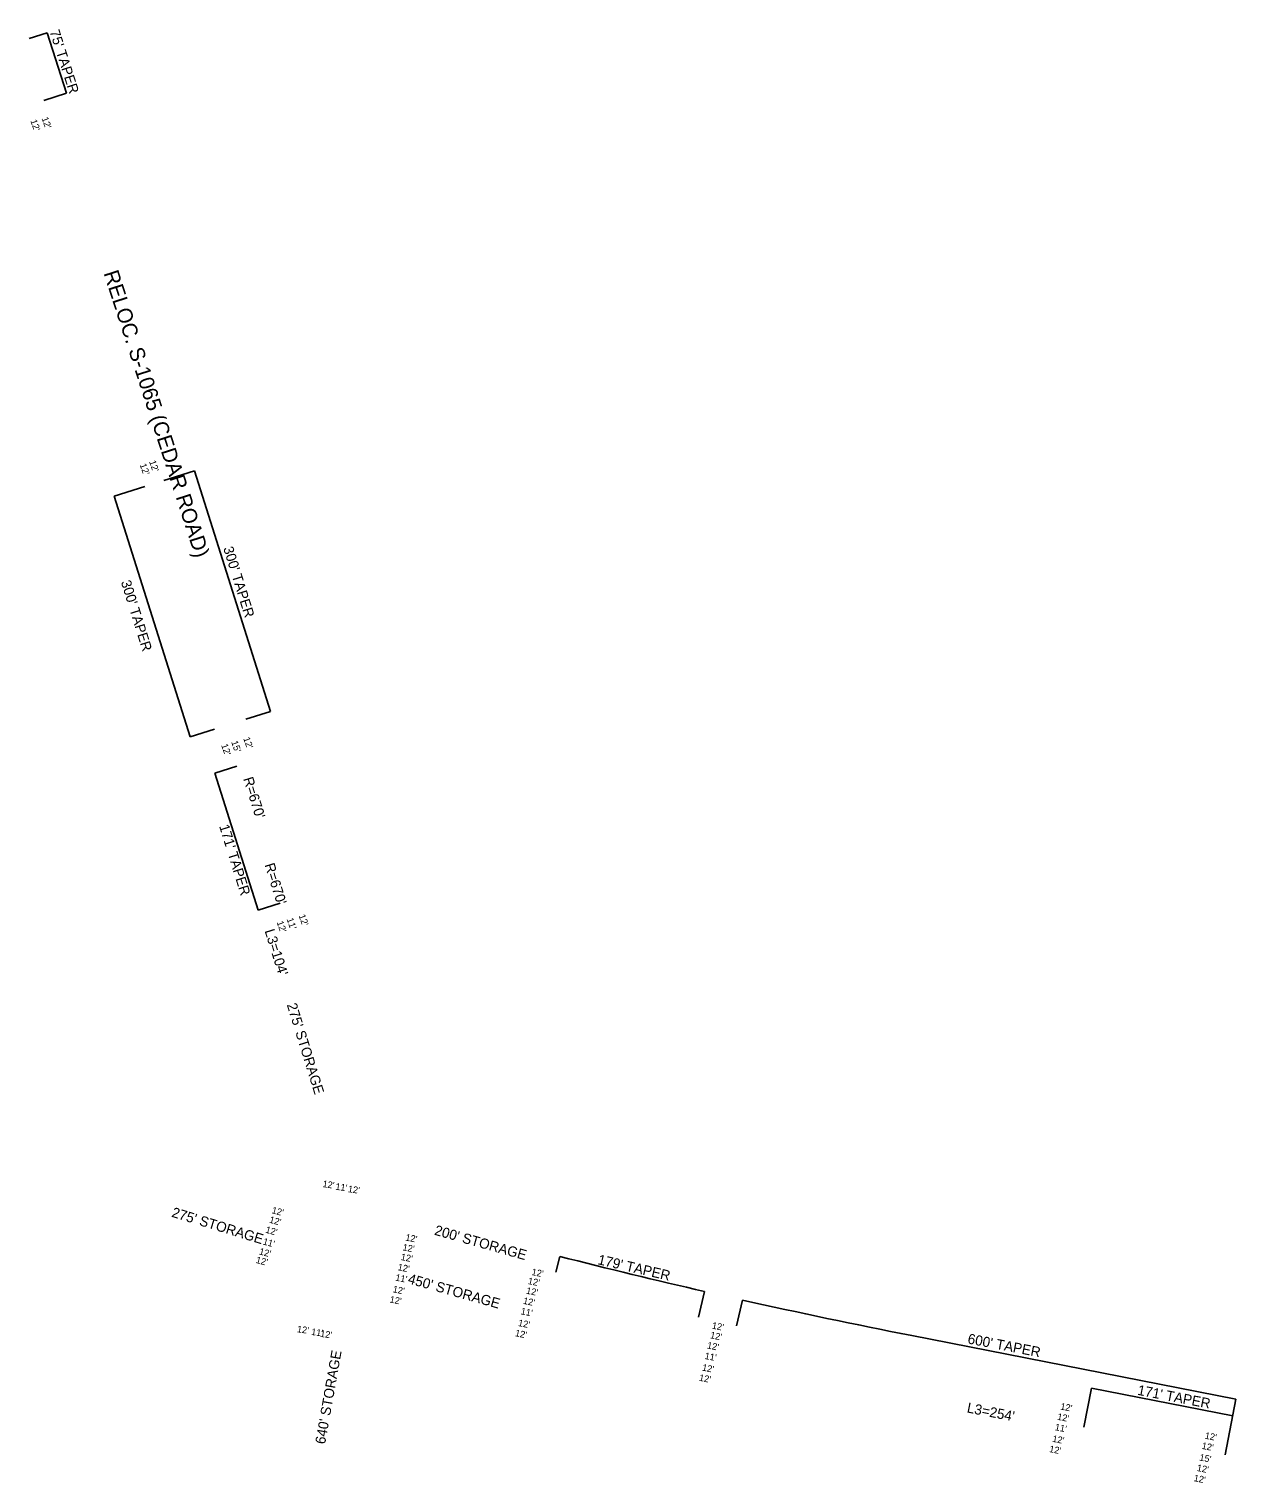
# Model space of a CAD drawing. Extents: x 1938363 to 1944069, y 778949 to 784066.
# Drawn here: x 1942634 to 1944069, y 779873 to 781602 of the extents above; entities that cross this region are included whole.
import ezdxf

# ---------------------------------------------------------------- set-up
doc = ezdxf.new("R2010")
doc.units = 0
doc.layers.add('RD_PD_Final_TX', color=7, linetype='Continuous')
doc.layers.add('RD_TX_RoadID', color=7, linetype='Continuous')

msp = doc.modelspace()

# ---------------------------------------------------------------- linework, layer by layer
at = {"layer": 'RD_PD_Final_TX'}
for p, q in [((1942633.6, 781590.7), (1942655.3, 781597.5)), ((1942655.3, 781597.5), (1942678, 781525.7)), ((1942651.3, 781517.2), (1942678, 781525.7)), ((1942830.3, 781076.7), (1942794, 781065.3)), ((1942830.3, 781076.7), (1942920.7, 780790.5)), ((1942771.2, 781058), (1942734.9, 781046.6)), ((1942734.9, 781046.6), (1942825.3, 780760.4)), ((1942920.7, 780790.5), (1942891.6, 780781.3)), ((1942854.4, 780769.6), (1942825.3, 780760.4)), ((1942880.9, 780725.5), (1942854.7, 780717.2)), ((1942854.7, 780717.2), (1942906.2, 780554.2)), ((1942932.4, 780562.4), (1942906.2, 780554.2)), ((1943260.2, 780123.5), (1943265, 780142.4)), ((1943430.2, 780070), (1943437.3, 780100.7)), ((1943475.4, 780059.7), (1943482.3, 780090.5)), ((1943683.7, 780048.2), (1944069.4, 779972.5)), ((1943888.6, 779939.2), (1943897.7, 779985.8)), ((1943897.7, 779985.8), (1944065.5, 779952.9)), ((1944056.4, 779906.3), (1944069.4, 779972.5))]:
    msp.add_line(p, q, dxfattribs=at)
for start, end in [(255.74647, 257.04964), (257.38869, 258.90156)]:
    msp.add_arc((1945184.2, 787697.4), 7795, start, end, dxfattribs=at)

# ---------------------------------------------------------------- texts
for s, height, rotation, p in [("75' TAPER", 12, 287.712, (1942657.9, 781599.2)), ("12'", 8, 289.542, (1942635, 781493.1)), ("12'", 8, 289.542, (1942648.4, 781496)), ("12'", 8, 289.542, (1942776.3, 781087.7)), ("12'", 8, 289.542, (1942765.1, 781083.9)), ("300' TAPER", 12, 287.3319, (1942864.5, 780984.7)), ("300' TAPER", 12, 287.3319, (1942742.7, 780944.6)), ("12'", 8, 289.542, (1942888.3, 780758.5)), ("12'", 8, 289.542, (1942862, 780750.5)), ("15'", 8, 289.542, (1942874, 780754.2)), ("R=670'", 12, 287.3319, (1942888.3, 780710.5)), ("171' TAPER", 12, 287.3319, (1942859.6, 780654.2)), ("R=670'", 12, 287.3319, (1942913.7, 780608.1)), ("12'", 8, 289.542, (1942928, 780539.8)), ("11'", 8, 289.542, (1942939.9, 780543.5)), ("12'", 8, 289.542, (1942954.2, 780547.7)), ("L3=104'", 12, 287.3319, (1942913.7, 780529.6)), ("275' STORAGE", 12, 287.2227, (1942940.1, 780441.7)), ("12'", 8, 351.606, (1942982.4, 780224.9)), ("11'", 8, 351.606, (1942997.7, 780221.8)), ("12'", 8, 351.606, (1943012.6, 780218.9)), ("275' STORAGE", 12, 343.0326, (1942802.4, 780189.7)), ("12'", 8, 345.0511, (1942918.8, 780182.6)), ("12'", 8, 345.0511, (1942921.7, 780193.9)), ("12'", 8, 345.0511, (1942914.3, 780170.7)), ("200' STORAGE", 12, 344.3329, (1943115, 780168.3)), ("11'", 8, 345.0511, (1942911.2, 780156.7)), ("12'", 8, 348.9016, (1943077.5, 780149.7)), ("12'", 8, 348.9016, (1943080.8, 780161.4)), ("12'", 8, 345.0511, (1942902.8, 780134.8)), ("12'", 8, 345.0511, (1942906.7, 780144.9)), ("12'", 8, 348.9016, (1943075.4, 780138.2)), ("179' TAPER", 12, 346.9376, (1943309.4, 780133.2)), ("11'", 8, 348.9016, (1943068.9, 780113.7)), ("12'", 8, 348.9016, (1943071.7, 780126.1)), ("450' STORAGE", 12, 344.3329, (1943083.4, 780110.6)), ("12'", 8, 348.9016, (1943231, 780120.3)), ("12'", 8, 348.9016, (1943065.8, 780099.8)), ("12'", 8, 348.9016, (1943224.5, 780098.1)), ("12'", 8, 348.9016, (1943226.6, 780109.6)), ("12'", 8, 348.9016, (1943062.1, 780087.7)), ("12'", 8, 348.9016, (1943220.9, 780086)), ("11'", 8, 348.9016, (1943218.1, 780073.6)), ("12'", 8, 351.606, (1942952, 780052.3)), ("11'", 8, 351.606, (1942968.9, 780049.1)), ("12'", 8, 351.606, (1942979.6, 780046.8)), ("12'", 8, 348.9016, (1943211.3, 780047.6)), ("12'", 8, 348.9016, (1943215, 780059.7)), ("12'", 8, 348.9016, (1943443.4, 780045.1)), ("12'", 8, 348.9016, (1943445.5, 780056.6)), ("600' TAPER", 12, 349.0875, (1943749.5, 780039)), ("12'", 8, 348.9016, (1943439.7, 780033)), ("640' STORAGE", 12, 79.8923, (1942985.7, 779918.5)), ("11'", 8, 348.9016, (1943436.9, 780020.5)), ("12'", 8, 348.9016, (1943430.2, 779994.6)), ("12'", 8, 348.9016, (1943433.8, 780006.7)), ("171' TAPER", 12, 349.0875, (1943951.6, 779977.9)), ("L3=254'", 12, 349.0875, (1943748.7, 779956.9)), ("12'", 8, 348.9016, (1943860, 779960.4)), ("12'", 8, 348.9016, (1943856.3, 779948.2)), ("12'", 8, 348.9016, (1943850.5, 779922)), ("11'", 8, 348.9016, (1943853.5, 779935.8)), ("12'", 8, 348.9016, (1944031.9, 779925.7)), ("12'", 8, 348.9016, (1943846.8, 779909.8)), ("12'", 8, 348.9016, (1944028.2, 779913.6)), ("15'", 8, 348.9016, (1944025.4, 779899.8)), ("12'", 8, 348.9016, (1944018.7, 779875.2)), ("12'", 8, 348.9016, (1944022.4, 779887.3))]:
    msp.add_text(s, height=height, rotation=rotation, dxfattribs=at).set_placement(p)
at = {"layer": 'RD_TX_RoadID'}
msp.add_text('RELOC. S-1065 (CEDAR ROAD)', height=18, rotation=287.8619, dxfattribs=at).set_placement((1942722.1, 781311.9))

doc.saveas('drawing.dxf')
